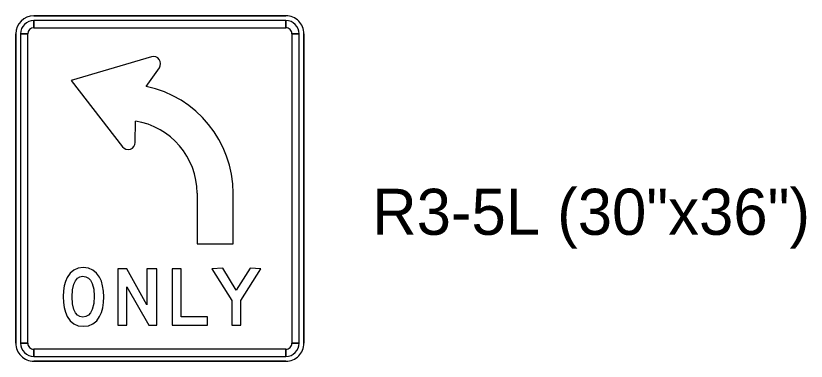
# Model space of a CAD drawing. Extents: x 620856.8 to 620948.6, y 415598.8 to 415658.2.
# Drawn here: x 620902.06 to 620908.91, y 415627.78 to 415630.78 of the extents above; entities that cross this region are included whole.
import ezdxf

# ---------------------------------------------------------------- set-up
doc = ezdxf.new("R2010")
doc.units = 0
doc.layers.add('SIGNS', color=7, linetype='Continuous')

msp = doc.modelspace()

# ---------------------------------------------------------------- linework, layer by layer
at = {"layer": 'SIGNS'}
for p, q in [((620904.4014, 415630.7793), (620902.2139, 415630.7793)), ((620902.2139, 415630.7793), (620904.4014, 415630.7793)), ((620902.2139, 415630.6751), (620902.2139, 415630.7376)), ((620904.4014, 415630.7376), (620904.4014, 415630.6751)), ((620902.0577, 415630.623), (620902.0577, 415627.9355)), ((620902.0577, 415627.9355), (620902.0577, 415630.623)), ((620902.0993, 415630.623), (620902.1618, 415630.623)), ((620904.4535, 415630.623), (620904.516, 415630.623)), ((620904.5577, 415627.9355), (620904.5577, 415630.623)), ((620904.5577, 415630.623), (620904.5577, 415627.9355)), ((620903.234, 415630.4242), (620902.5368, 415630.2168)), ((620903.1882, 415630.1657), (620903.3029, 415630.3282)), ((620902.5368, 415630.2168), (620902.9822, 415629.6417)), ((620903.0941, 415629.6795), (620903.0956, 415629.865)), ((620903.6306, 415629.2376), (620903.6306, 415628.8001)), ((620903.9431, 415628.8001), (620903.9431, 415629.2376)), ((620903.6306, 415628.8001), (620903.9431, 415628.8001)), ((620902.1618, 415627.9355), (620902.0993, 415627.9355)), ((620904.516, 415627.9355), (620904.4535, 415627.9355)), ((620902.2139, 415627.8209), (620902.2139, 415627.8834)), ((620904.4014, 415627.8834), (620904.4014, 415627.8209)), ((620902.2139, 415627.7793), (620904.4014, 415627.7793)), ((620904.4014, 415627.7793), (620902.2139, 415627.7793))]:
    msp.add_line(p, q, dxfattribs=at)
for points in [[(620904.4014, 415630.7376), (620902.2139, 415630.7376), (620902.2139, 415630.6751), (620904.4014, 415630.6751), (620904.4014, 415630.7376), (620904.4014, 415630.7376)], [(620902.0993, 415630.623), (620902.0993, 415627.9355), (620902.1618, 415627.9355), (620902.1618, 415630.623), (620902.0993, 415630.623), (620902.0993, 415630.623)], [(620904.516, 415627.9355), (620904.516, 415630.623), (620904.4535, 415630.623), (620904.4535, 415627.9355), (620904.516, 415627.9355), (620904.516, 415627.9355)], [(620902.9442, 415628.0918), (620903.0211, 415628.0918), (620903.0211, 415628.4265), (620903.2107, 415628.0918), (620903.2804, 415628.0918), (620903.2804, 415628.5821), (620903.1942, 415628.5821), (620903.1942, 415628.2703), (620903.0211, 415628.5821), (620902.9442, 415628.5821)], [(620903.4152, 415628.0918), (620903.7218, 415628.0918), (620903.7218, 415628.1634), (620903.4914, 415628.1634), (620903.4914, 415628.5821), (620903.4152, 415628.5821)], [(620903.7579, 415628.5821), (620903.9325, 415628.306), (620903.9325, 415628.0918), (620904.0106, 415628.0918), (620904.0106, 415628.306), (620904.1832, 415628.5821), (620904.0907, 415628.5862), (620903.9706, 415628.3965), (620903.8524, 415628.5862)], [(620902.2139, 415627.8209), (620904.4014, 415627.8209), (620904.4014, 415627.8834), (620902.2139, 415627.8834), (620902.2139, 415627.8209), (620902.2139, 415627.8209)]]:
    msp.add_lwpolyline(points, close=True, dxfattribs=at)
for points in [[(620902.8202, 415628.3373), (620902.8179, 415628.3885), (620902.8111, 415628.4343), (620902.8, 415628.4746), (620902.7846, 415628.5096), (620902.7587, 415628.5453), (620902.7263, 415628.5712), (620902.6872, 415628.5865), (620902.6417, 415628.5918), (620902.5977, 415628.5865), (620902.5601, 415628.5707), (620902.5287, 415628.5444), (620902.5036, 415628.5076), (620902.4884, 415628.4726), (620902.4776, 415628.4333), (620902.4712, 415628.3891), (620902.4691, 415628.3406), (620902.4712, 415628.2901), (620902.4776, 415628.2447), (620902.4884, 415628.2043), (620902.5036, 415628.1688), (620902.5292, 415628.1308), (620902.5613, 415628.1037), (620902.6001, 415628.0876), (620902.6456, 415628.0822), (620902.6895, 415628.0875), (620902.7273, 415628.1035), (620902.7592, 415628.1302), (620902.785, 415628.1678), (620902.8003, 415628.2034), (620902.8113, 415628.2436), (620902.8179, 415628.2881), (620902.8202, 415628.3373)], [(620902.7383, 415628.3429), (620902.7339, 415628.2798), (620902.721, 415628.2283), (620902.7065, 415628.1995), (620902.688, 415628.1789), (620902.6656, 415628.1666), (620902.6394, 415628.1625), (620902.6144, 415628.1666), (620902.5932, 415628.1789), (620902.5757, 415628.1995), (620902.5622, 415628.2283), (620902.55, 415628.2784), (620902.546, 415628.339), (620902.55, 415628.3989), (620902.5622, 415628.4492), (620902.5756, 415628.4786), (620902.5927, 415628.4997), (620902.6133, 415628.5123), (620902.6375, 415628.5165), (620902.6641, 415628.5126), (620902.6869, 415628.5011), (620902.7057, 415628.4819), (620902.7206, 415628.4552), (620902.7338, 415628.4053), (620902.7383, 415628.3429)]]:
    msp.add_lwpolyline(points, dxfattribs=at)
for centre, radius, start, end in [((620902.2139, 415630.623), 0.1562, 90.00021, 179.99985), ((620902.2139, 415630.623), 0.1562, 90.00021, 179.99985), ((620902.2139, 415630.623), 0.1146, 90.00021, 179.99985), ((620904.4014, 415630.623), 0.1562, 360, 90.00021), ((620904.4014, 415630.623), 0.1562, 360, 90.00021), ((620904.4014, 415630.623), 0.1146, 360, 90.00021), ((620902.2139, 415630.623), 0.0521, 90.00021, 179.99985), ((620904.4014, 415630.623), 0.0521, 360, 90.00021), ((620903.2518, 415630.3642), 0.0625, 324.79373, 106.56526), ((620902.9952, 415629.2376), 0.9479, 0.00027, 78.25083), ((620902.9952, 415629.2376), 0.6354, 0.00027, 80.9042), ((620903.0316, 415629.68), 0.0625, 217.75433, 359.52586), ((620902.2139, 415627.9355), 0.1562, 179.99985, 270.00006), ((620902.2139, 415627.9355), 0.1562, 179.99985, 270.00006), ((620902.2139, 415627.9355), 0.1146, 179.99985, 270.00006), ((620902.2139, 415627.9355), 0.0521, 179.99985, 270.00006), ((620904.4014, 415627.9355), 0.1562, 270.00006, 0.00027), ((620904.4014, 415627.9355), 0.1146, 270.00006, 0.00027), ((620904.4014, 415627.9355), 0.0521, 270.00006, 0.00027), ((620904.4014, 415627.9355), 0.1562, 270.00006, 0.00027)]:
    msp.add_arc(centre, radius, start, end, dxfattribs=at)

# ---------------------------------------------------------------- texts
msp.add_text('R3-5L (30"x36")', height=0.4, rotation=0, dxfattribs=at).set_placement((620905.1492, 415628.877))

doc.saveas('drawing.dxf')
